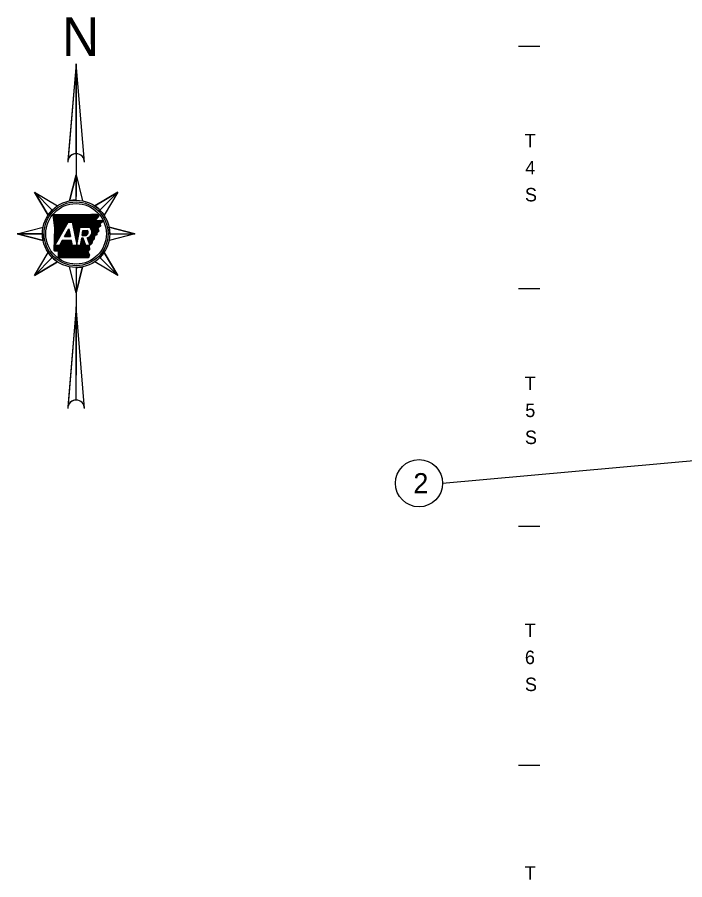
# Model space of a CAD drawing. Extents: x -42408 to 34530, y -43140 to 20491.
# Drawn here: x 3373 to 6343, y -27968 to -24133 of the extents above; entities that cross this region are included whole.
import ezdxf

# ---------------------------------------------------------------- set-up
doc = ezdxf.new("R2010")
doc.units = 0
for name, color, linetype in [('2', 7, 'Continuous'), ('30', 7, 'Continuous'), ('9', 7, 'Continuous'), ('Default', 7, 'Continuous')]:
    doc.layers.add(name, color=color, linetype=linetype)

msp = doc.modelspace()

# ---------------------------------------------------------------- linework, layer by layer
at = {"layer": '30'}
msp.add_line((5265.6, -26204.7), (7391.4, -26011.8), dxfattribs=at)
msp.add_circle((5160.6, -26204.7), 105, dxfattribs=at)
at = {"layer": '9'}
for p, q in [((3635, -24339.1), (3598.2, -24770.3)), ((3635, -24339.1), (3635, -24929.6)), ((3635, -24739.2), (3635, -24339.1)), ((3598.7, -24764.2), (3600.4, -24762.6)), ((3598.9, -24761.9), (3602.3, -24758.5)), ((3635, -24833.7), (3605.9, -24948.8)), ((3635, -24945.9), (3635, -24833.7)), ((3449.9, -24910.4), (3529.3, -24989.7)), ((3529.3, -24989.7), (3449.9, -24910.4)), ((3449.9, -24910.4), (3510.7, -25012.4)), ((3820.1, -24910.4), (3718.2, -24971.2)), ((3740.8, -24989.7), (3820.1, -24910.4)), ((3740.8, -24989.7), (3820.1, -24910.4)), ((3533.1, -25011.2), (3534.4, -25009.9)), ((3533.5, -25015), (3538.6, -25009.9)), ((3534, -25018.7), (3542.9, -25009.9)), ((3534.5, -25022.5), (3547.1, -25009.9)), ((3535, -25026.3), (3551.3, -25009.9)), ((3535.4, -25030), (3555.5, -25009.9)), ((3535.9, -25033.8), (3559.8, -25009.9)), ((3536.4, -25037.5), (3564, -25009.9)), ((3536.8, -25041.3), (3568.2, -25009.9)), ((3537.3, -25045.1), (3572.5, -25009.9)), ((3537.8, -25048.8), (3576.7, -25009.9)), ((3538.2, -25052.6), (3580.9, -25009.9)), ((3538.7, -25056.4), (3585.1, -25009.9)), ((3539.2, -25060.1), (3589.4, -25009.9)), ((3539.3, -25102.3), (3631.8, -25009.8)), ((3539.5, -25097.9), (3627.5, -25009.8)), ((3539.6, -25093.5), (3623.3, -25009.9)), ((3539.6, -25063.9), (3593.6, -25009.9)), ((3539.7, -25089.2), (3619, -25009.9)), ((3539.9, -25084.8), (3614.8, -25009.9)), ((3540, -25080.4), (3610.6, -25009.9)), ((3540.1, -25067.6), (3597.8, -25009.9)), ((3540.2, -25076), (3606.3, -25009.9)), ((3540.3, -25071.7), (3602.1, -25009.9)), ((3540.6, -25147.9), (3599.6, -25043.7)), ((3599.6, -25043.7), (3617.1, -25043.7)), ((3602.1, -25043.7), (3636, -25009.8)), ((3606.4, -25043.7), (3640.2, -25009.8)), ((3610.6, -25043.7), (3644.5, -25009.8)), ((3614.8, -25043.7), (3648.8, -25009.7)), ((3617.5, -25045.3), (3653.1, -25009.6)), ((3618.2, -25048.8), (3657.4, -25009.6)), ((3619, -25052.3), (3661.7, -25009.5)), ((3619.7, -25055.7), (3666, -25009.4)), ((3620.4, -25059.2), (3670.3, -25009.4)), ((3621.2, -25062.7), (3674.6, -25009.3)), ((3621.9, -25066.2), (3678.9, -25009.2)), ((3622.7, -25069.7), (3683.2, -25009.2)), ((3623.4, -25073.2), (3687.5, -25009.1)), ((3624.2, -25076.6), (3691.8, -25009)), ((3624.9, -25080.1), (3696.1, -25009)), ((3625.7, -25083.6), (3700.4, -25008.9)), ((3626.4, -25087.1), (3704.7, -25008.8)), ((3627.2, -25090.6), (3709, -25008.7)), ((3656.6, -25065.4), (3713.3, -25008.6)), ((3660.8, -25065.4), (3717.7, -25008.5)), ((3665, -25065.4), (3722, -25008.4)), ((3669.2, -25065.4), (3726.3, -25008.3)), ((3673.5, -25065.4), (3730.7, -25008.2)), ((3677.7, -25065.4), (3731.6, -25011.5)), ((3681.9, -25065.4), (3733.7, -25013.7)), ((3686.2, -25065.4), (3734.2, -25017.4)), ((3690.4, -25065.4), (3724.5, -25031.3)), ((3694.2, -25065.8), (3723.7, -25036.3)), ((3696.6, -25067.7), (3728.2, -25036.1)), ((3698.6, -25069.9), (3732.6, -25035.9)), ((3700.4, -25072.3), (3737.1, -25035.7)), ((3702, -25075), (3741.6, -25035.4)), ((3703.3, -25077.9), (3746, -25035.2)), ((3704.3, -25081.2), (3750, -25035.4)), ((3704.9, -25084.8), (3752, -25037.7)), ((3750.1, -25043.8), (3754, -25039.9)), ((3538.7, -25119.8), (3579.7, -25078.8)), ((3538.9, -25115.4), (3585.2, -25069.1)), ((3539, -25111), (3590.7, -25059.3)), ((3539.2, -25106.7), (3596.3, -25049.6)), ((3584, -25107), (3603.3, -25072.9)), ((3589.2, -25097.7), (3605.2, -25081.8)), ((3594.8, -25088), (3604.4, -25078.3)), ((3600.3, -25078.2), (3603.7, -25074.8)), ((3627.9, -25094.1), (3651.9, -25070.1)), ((3628.7, -25097.6), (3651, -25075.2)), ((3629.4, -25101), (3650.1, -25080.3)), ((3652.7, -25065.4), (3693.7, -25065.4)), ((3661.6, -25102.4), (3683.9, -25080.1)), ((3662.5, -25097.3), (3679.7, -25080.1)), ((3663.4, -25092.2), (3675.4, -25080.1)), ((3664.3, -25087.1), (3671.2, -25080.1)), ((3665.2, -25081.9), (3667, -25080.1)), ((3665.5, -25080.1), (3684.7, -25080.1)), ((3665.9, -25102.4), (3686.3, -25082)), ((3686.5, -25120.1), (3733.4, -25073.2)), ((3687.7, -25123.2), (3734.2, -25076.6)), ((3688.8, -25126.2), (3735, -25080)), ((3690, -25129.3), (3735.8, -25083.5)), ((3700.3, -25102.1), (3732.6, -25069.7)), ((3704, -25094.1), (3742.4, -25055.7)), ((3704.9, -25089), (3741.9, -25052)), ((3737.7, -25064.7), (3742.9, -25059.5)), ((3896.8, -25095.5), (3781.8, -25066.4)), ((3373.3, -25095.5), (3485.5, -25095.5)), ((3485.5, -25095.5), (3373.3, -25095.5)), ((3373.3, -25095.5), (3488.3, -25124.6)), ((3538.1, -25137.3), (3557.6, -25117.8)), ((3538.3, -25132.9), (3563.1, -25108.1)), ((3538.4, -25128.5), (3568.6, -25098.3)), ((3538.6, -25124.2), (3574.2, -25088.6)), ((3584, -25107), (3610.6, -25107)), ((3584.2, -25107), (3605.9, -25085.3)), ((3588.4, -25107), (3606.7, -25088.7)), ((3592.6, -25107), (3607.4, -25092.2)), ((3596.9, -25107), (3608.2, -25095.7)), ((3601.1, -25107), (3608.9, -25099.2)), ((3605.3, -25107), (3609.7, -25102.7)), ((3609.6, -25107), (3610.4, -25106.2)), ((3630.1, -25104.5), (3649.2, -25085.4)), ((3630.9, -25108), (3648.3, -25090.6)), ((3631.6, -25111.5), (3647.5, -25095.7)), ((3632.4, -25115), (3646.6, -25100.8)), ((3633.1, -25118.5), (3645.7, -25105.9)), ((3633.9, -25122), (3644.8, -25111.1)), ((3634.6, -25125.4), (3643.9, -25116.2)), ((3635.4, -25128.9), (3643, -25121.3)), ((3656.2, -25133.5), (3668.8, -25120.9)), ((3657.1, -25128.3), (3667.7, -25117.8)), ((3658, -25123.2), (3666.4, -25114.8)), ((3658.9, -25118.1), (3662.2, -25114.8)), ((3666.6, -25114.8), (3659.5, -25114.8)), ((3661.6, -25102.4), (3679.2, -25102.4)), ((3678.8, -25147.9), (3666.6, -25114.8)), ((3670.1, -25102.4), (3687.7, -25084.8)), ((3674.3, -25102.4), (3688.5, -25088.3)), ((3678.6, -25102.4), (3688.1, -25092.9)), ((3683.9, -25113), (3696.8, -25147.9)), ((3684.2, -25113.9), (3685.5, -25112.6)), ((3685.4, -25117), (3693.4, -25108.9)), ((3691.1, -25132.4), (3716.5, -25107)), ((3692.2, -25135.5), (3716, -25111.8)), ((3693.4, -25138.6), (3715.5, -25116.5)), ((3721.3, -25102.2), (3727.3, -25096.2)), ((3784.6, -25095.5), (3896.8, -25095.5)), ((3784.6, -25095.5), (3896.8, -25095.5)), ((3537.2, -25167.9), (3557.1, -25147.9)), ((3537.3, -25163.5), (3552.9, -25147.9)), ((3537.4, -25159.2), (3548.7, -25147.9)), ((3537.6, -25154.8), (3544.4, -25147.9)), ((3537.7, -25150.4), (3541, -25147.1)), ((3537.9, -25146), (3546.5, -25137.4)), ((3538, -25141.7), (3552.1, -25127.6)), ((3538.8, -25170.5), (3583.2, -25126)), ((3560.8, -25147.9), (3540.6, -25147.9)), ((3541.3, -25172.2), (3587.5, -25126)), ((3544.3, -25173.4), (3591.7, -25126)), ((3549.4, -25172.6), (3595.9, -25126)), ((3553.7, -25172.6), (3600.2, -25126)), ((3557, -25173.5), (3604.4, -25126)), ((3557.1, -25181.8), (3612.9, -25126)), ((3557.1, -25177.6), (3608.6, -25126)), ((3557.1, -25186), (3615.1, -25128)), ((3557.1, -25190.2), (3615.8, -25131.5)), ((3557.1, -25194.4), (3616.6, -25135)), ((3557.2, -25198.7), (3617.3, -25138.5)), ((3557.2, -25202.8), (3618.1, -25142)), ((3573.2, -25126), (3560.8, -25147.9)), ((3561.5, -25202.8), (3618.8, -25145.5)), ((3565.6, -25139.4), (3579, -25126)), ((3565.7, -25202.8), (3620.6, -25147.9)), ((3569.9, -25202.8), (3624.8, -25147.9)), ((3571.1, -25129.7), (3574.8, -25126)), ((3614.7, -25126), (3573.2, -25126)), ((3574.1, -25202.9), (3629.1, -25147.9)), ((3578.4, -25202.9), (3633.3, -25147.9)), ((3582.6, -25202.9), (3637.5, -25147.9)), ((3586.8, -25202.9), (3641.8, -25147.9)), ((3591, -25202.9), (3646, -25147.9)), ((3595.2, -25202.9), (3650.2, -25147.9)), ((3599.5, -25202.9), (3672.2, -25130.1)), ((3603.7, -25202.9), (3673.4, -25133.2)), ((3607.9, -25202.9), (3674.5, -25136.3)), ((3612.1, -25202.9), (3675.7, -25139.4)), ((3616.4, -25202.9), (3676.8, -25142.5)), ((3653.7, -25147.9), (3619.3, -25147.9)), ((3620.6, -25202.9), (3677.9, -25145.6)), ((3624.8, -25202.9), (3679.8, -25147.9)), ((3629, -25202.9), (3684.1, -25147.9)), ((3633.3, -25203), (3688.3, -25147.9)), ((3636.1, -25132.4), (3642.1, -25126.4)), ((3636.9, -25135.9), (3641.2, -25131.6)), ((3637.5, -25203), (3692.5, -25147.9)), ((3637.6, -25139.4), (3640.3, -25136.7)), ((3638.3, -25142.9), (3639.4, -25141.8)), ((3641.7, -25203), (3693.9, -25150.7)), ((3645.9, -25203), (3694.1, -25154.8)), ((3650.2, -25203), (3694.3, -25158.8)), ((3654.4, -25143.7), (3671.1, -25127)), ((3655.3, -25138.6), (3670, -25123.9)), ((3696.8, -25147.9), (3678.8, -25147.9)), ((3694.5, -25141.7), (3707.5, -25128.7)), ((3695.7, -25144.8), (3705.7, -25134.8)), ((3654.4, -25203), (3694.5, -25162.9)), ((3658.6, -25203), (3687.6, -25174)), ((3662.8, -25203), (3688.9, -25177)), ((3667.1, -25203), (3690.2, -25179.9)), ((3671.3, -25203), (3691.5, -25182.8)), ((3675.5, -25203), (3692.8, -25185.7)), ((3679.7, -25203), (3693.9, -25188.9)), ((3684, -25203), (3692, -25195)), ((3820.1, -25280.6), (3759.4, -25178.7)), ((3449.9, -25280.6), (3529.3, -25201.3)), ((3529.3, -25201.3), (3449.9, -25280.6)), ((3449.9, -25280.6), (3551.9, -25219.9)), ((3688.2, -25203), (3690.1, -25201.2)), ((3740.8, -25201.3), (3820.1, -25280.6)), ((3740.8, -25201.3), (3820.1, -25280.6)), ((3635, -25357.3), (3664.2, -25242.2)), ((3635, -25245.1), (3635, -25245.1)), ((3635, -25245.1), (3635, -25724)), ((3635, -25245.1), (3635, -25357.3)), ((3635, -25419.8), (3598.1, -25866.2)), ((3635, -25834.9), (3635, -25419.8))]:
    msp.add_line(p, q, dxfattribs=at)
for points in [[(3672.4, -24776.6), (3635, -24339.1), (3597.6, -24776.6)], [(3605.9, -24948.8), (3635, -24833.7), (3664.2, -24948.8)], [(3510.7, -25012.4), (3449.9, -24910.4), (3551.9, -24971.2)], [(3718.2, -24971.2), (3820.1, -24910.4), (3759.4, -25012.4)], [(3532.9, -25009.9), (3591.3, -25009.9), (3642.5, -25009.8), (3702.9, -25008.9), (3730.9, -25008.2)], [(3537.1, -25167.8), (3540.4, -25069.9), (3532.9, -25009.9)], [(3617.1, -25043.7), (3638.8, -25145.1), (3652.7, -25065.4)], [(3749.3, -25035), (3754.3, -25040.3), (3741.7, -25050.7), (3743.1, -25061.1), (3732.3, -25068.2), (3736, -25084.3), (3727.7, -25091.9), (3726.9, -25100.2), (3716.8, -25103.8), (3715.2, -25119.4), (3708, -25127.2), (3704.4, -25138.9), (3693.8, -25148.6), (3694.6, -25165.7), (3687.5, -25173.8), (3694, -25188.5), (3689.5, -25203)], [(3722.3, -25036.4), (3749.7, -25035)], [(3488.3, -25124.6), (3373.3, -25095.5), (3488.3, -25066.4)], [(3603.3, -25072.9), (3610.6, -25107)], [(3661.6, -25102.4), (3665.5, -25080.1)], [(3781.8, -25066.4), (3896.8, -25095.5), (3781.8, -25124.6)], [(3659.5, -25114.8), (3653.7, -25147.9)], [(3619.3, -25147.9), (3614.7, -25126)], [(3551.9, -25219.9), (3449.9, -25280.6), (3510.7, -25178.7)], [(3689.5, -25203), (3557.2, -25202.8), (3557.1, -25173.6)], [(3759.4, -25178.7), (3820.1, -25280.6), (3718.2, -25219.9)], [(3664.2, -25242.2), (3635, -25357.3), (3605.9, -25242.2)], [(3672.4, -25872.3), (3635, -25419.8), (3597.6, -25872.3)]]:
    msp.add_lwpolyline(points, dxfattribs=at)
for radius in [149.6, 142.1, 134.6]:
    msp.add_circle((3635, -25095.5), radius, dxfattribs=at)
for centre, radius, start, end in [((3635, -24776.6), 37.4, 0, 180), ((3635, -24776.6), 37.4, 90, 170.2296), ((3635, -25095.5), 149.6, 90, 101.2291), ((3635, -25095.5), 149.6, 135, 146.2291), ((3635, -25095.5), 149.6, 45, 56.2291), ((3675, -25089.5), 13.5, 288.1268, 43.8902), ((3678.5, -25087.1), 26.5, 281.8626, 54.8705), ((3635, -25095.5), 149.6, 0, 11.2291), ((3635, -25095.5), 149.6, 180, 191.2291), ((3635, -25095.5), 149.6, 315, 326.2291), ((3635, -25095.5), 149.6, 225, 236.2291), ((3635, -25095.5), 149.6, 270, 281.2291), ((3635, -25872.3), 37.4, 0, 180), ((3635, -25872.3), 37.4, 90, 170.5511)]:
    msp.add_arc(centre, radius, start, end, dxfattribs=at)
for points in [[(3730.9, -25008.2), (3731.1, -25009.8), (3731.6, -25010.6), (3731.7, -25012.2), (3732.3, -25012.8), (3733.4, -25013.5), (3734.3, -25014.5), (3734.5, -25015.7), (3734.2, -25017), (3734.2, -25018.4), (3734, -25019.6), (3733.8, -25020.8), (3732.9, -25021.7), (3732.1, -25022.3), (3731.3, -25023.1), (3730.8, -25023.9), (3729.9, -25024.7), (3728.9, -25025.6), (3728.2, -25026.4), (3727.4, -25027.4), (3727, -25028.5), (3726.2, -25029.3), (3725.6, -25030.1), (3724.7, -25031), (3724.3, -25032), (3723.4, -25033.1), (3723.3, -25034.2), (3722.7, -25035.1), (3722.7, -25035.2)], [(3557.1, -25173.6), (3557.2, -25173.7), (3556.6, -25173.2), (3555.6, -25172.8), (3554.6, -25172.7), (3553.2, -25172.5), (3552.1, -25172.4), (3551, -25171.6), (3549.7, -25172.4), (3548.4, -25173), (3547.6, -25172.4), (3546.5, -25172.8), (3545.8, -25172.6), (3544.5, -25173.4), (3543.3, -25173.1), (3542.5, -25173.4), (3541.4, -25173.3), (3541.2, -25172.1), (3540.1, -25171.9), (3539.2, -25171.4), (3538.6, -25170.2), (3538.2, -25169.2), (3537.1, -25167.8)]]:
    msp.add_spline(points, degree=3, dxfattribs=at)
at = {"layer": 'Default'}
for p, q in [((5697.6, -24262.3), (5602.6, -24262.3)), ((5697.6, -25340.7), (5602.6, -25340.7)), ((5697.6, -26397.4), (5602.6, -26397.4)), ((5697.6, -27459.4), (5602.6, -27459.4))]:
    msp.add_line(p, q, dxfattribs=at)

# ---------------------------------------------------------------- texts
at = {"layer": '2'}
for s, p in [('T', (5630.5, -24711.5)), ('4', (5633.1, -24831.5)), ('S', (5631.6, -24951.5)), ('T', (5630.5, -25790.5)), ('5', (5633.1, -25910.5)), ('S', (5631.6, -26030.5)), ('T', (5630.5, -26889)), ('6', (5631.4, -27009)), ('S', (5631.6, -27129)), ('T', (5630.5, -27967.9))]:
    msp.add_text(s, height=60, dxfattribs=at).set_placement(p)
at = {"layer": '30'}
msp.add_text('2', height=90, dxfattribs=at).set_placement((5135.1, -26249.7))
at = {"layer": '9'}
for s, height, p in [('N', 172.6, (3572, -24305.1)), ('DWB 7-27-17', 2.909, (3625.9, -25232.6))]:
    msp.add_text(s, height=height, dxfattribs=at).set_placement(p)

doc.saveas('drawing.dxf')
